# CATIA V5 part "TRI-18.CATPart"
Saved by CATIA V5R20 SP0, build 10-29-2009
Part number: _TRI-18
Definition: NONE
Nomenclature: _TRI-18
Source: Unknown
Description: PART-_TRI-18-DESC
Bounding box of the stored display mesh (mm): x 0 to 22.5, y -9 to 9, z -9 to 9
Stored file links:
  C:\Users\Utente\Desktop\IO LAVORO\3D X SITO CF\X SITO\PLASTICA\TRI\TRI-18.CATPart
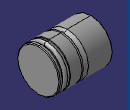
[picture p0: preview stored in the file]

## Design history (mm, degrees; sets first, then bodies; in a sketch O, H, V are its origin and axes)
Body1 "_TRI-18" (main body)
  Solid1: solid without history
